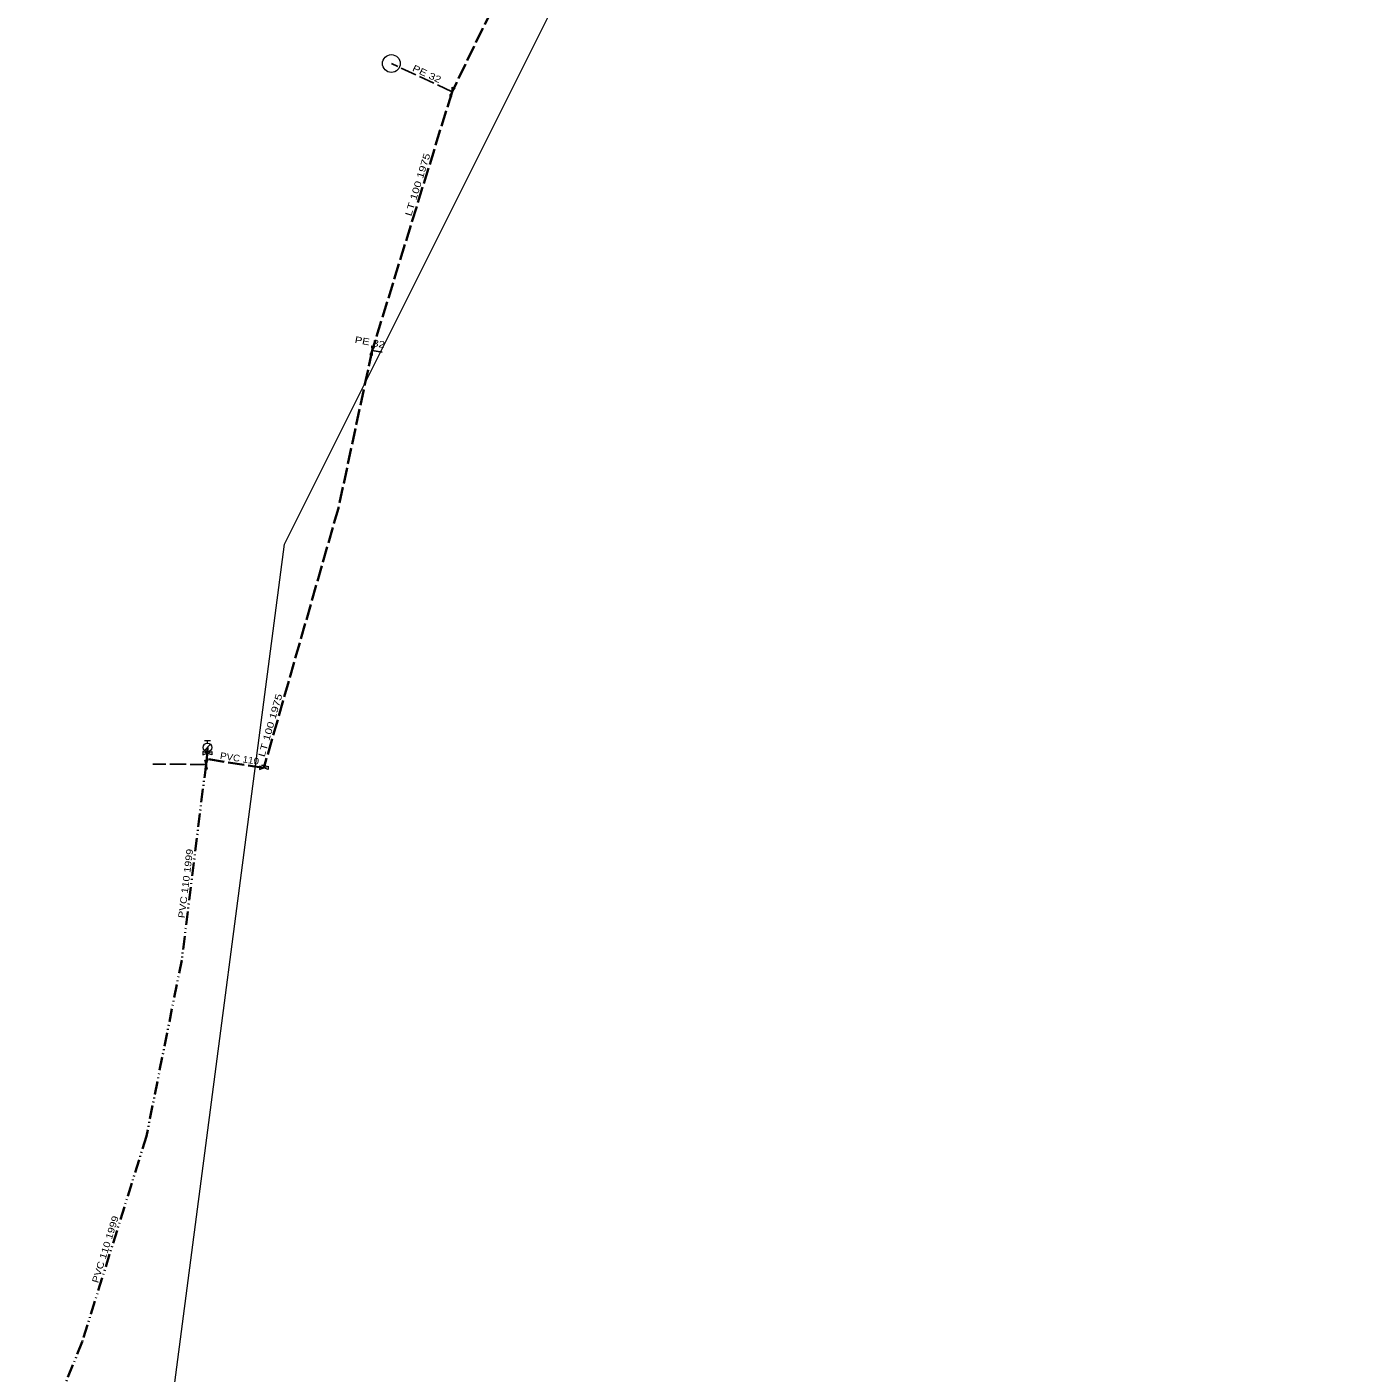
# Model space of a CAD drawing. Extents: x -582626 to -580899, y -1097611 to -1096610.
# Drawn here: x -581391.1 to -581240, y -1096912.4 to -1096761 of the extents above; entities that cross this region are included whole.
import ezdxf
from ezdxf.enums import TextEntityAlignment as Align

# ---------------------------------------------------------------- set-up
doc = ezdxf.new("R2010")
doc.units = 0
doc.header["$LTSCALE"] = 0.3
doc.linetypes.add('DASH_DOUBLE_DOT', pattern=[9.2, 5, -1.2, 0.3, -1.2, 0.3, -1.2])
doc.linetypes.add('LONG_DASHED', pattern=[7.5, 6, -1.5])
for name, color, linetype, lineweight in [('1', 7, 'Continuous', 13), ('10', 7, 'Continuous', 13), ('35', 7, 'LONG_DASHED', 35), ('36', 7, 'DASH_DOUBLE_DOT', 35), ('50', 7, 'LONG_DASHED', 25)]:
    doc.layers.add(name, color=color, linetype=linetype, lineweight=lineweight)
doc.layers.add('16', color=7, linetype='Continuous')
doc.layers.add('19', color=7, linetype='Continuous')

msp = doc.modelspace()

# ---------------------------------------------------------------- linework, layer by layer
at = {"layer": '1'}
msp.add_lwpolyline([(-582625.57, -1097394.66), (-582612.34, -1097467.421), (-582321.299, -1097262.369), (-581897.965, -1097202.837), (-581719.372, -1097182.994), (-581593.695, -1097110.233), (-581382.028, -1096971.327), (-581362.184, -1096819.192), (-581322.497, -1096739.817), (-581210.049, -1096733.202), (-581097.601, -1096686.9), (-580905.778, -1096719.973), (-580899.163, -1096627.369), (-581084.372, -1096614.14), (-581216.663, -1096680.285), (-581368.799, -1096686.9), (-581434.945, -1096812.577), (-581468.018, -1096971.327), (-581659.84, -1097004.4), (-581831.82, -1097110.233), (-582314.684, -1097169.765), (-582519.736, -1097295.442), (-582625.57, -1097394.66)], close=True, dxfattribs=at)
at = {"layer": '10'}
for p, q in [((-581371.181, -1096842.425), (-581370.474, -1096841.718)), ((-581371.177, -1096841.271), (-581370.477, -1096841.271)), ((-581370.827, -1096841.571), (-581370.827, -1096841.271)), ((-581370.85, -1096842.479), (-581371.1, -1096842.479)), ((-581364.487, -1096844.119), (-581364.737, -1096844.119))]:
    msp.add_line(p, q, dxfattribs=at)
for points in [[(-581343.31, -1096768.311), (-581343.291, -1096767.789), (-581343.007, -1096767.886), (-581343.31, -1096768.311), (-581343.613, -1096768.736), (-581343.329, -1096768.833)], [(-581352.301, -1096797.408), (-581352.334, -1096796.887), (-581352.042, -1096796.955), (-581352.301, -1096797.408), (-581352.56, -1096797.861), (-581352.268, -1096797.929)], [(-581370.994, -1096843.984), (-581371.144, -1096843.484), (-581370.844, -1096843.484), (-581370.994, -1096843.984), (-581371.144, -1096844.484), (-581370.844, -1096844.484)]]:
    msp.add_lwpolyline(points, close=True, dxfattribs=at)
for points in [[(-581370.85, -1096842.729), (-581370.35, -1096842.542), (-581370.35, -1096842.916), (-581370.85, -1096842.729), (-581371.35, -1096842.542), (-581371.35, -1096842.916), (-581370.85, -1096842.729), (-581370.85, -1096842.479), (-581370.6, -1096842.479)], [(-581364.487, -1096844.369), (-581363.987, -1096844.182), (-581363.987, -1096844.556), (-581364.487, -1096844.369), (-581364.987, -1096844.182), (-581364.987, -1096844.556), (-581364.487, -1096844.369), (-581364.487, -1096844.119), (-581364.237, -1096844.119)]]:
    msp.add_lwpolyline(points, dxfattribs=at)
for centre, radius in [((-581350.145, -1096765.14), 1), ((-581370.8268, -1096842.0707), 0.5)]:
    msp.add_circle(centre, radius, dxfattribs=at)
at = {"layer": '35'}
msp.add_line((-581364.487, -1096844.369), (-581370.918, -1096843.373), dxfattribs=at)
for points in [[(-581321.931, -1096700.577), (-581316.045, -1096715.422), (-581314.027, -1096722.581), (-581310.681, -1096727.605), (-581321.786, -1096737.077), (-581325.934, -1096741.538), (-581329.57, -1096745.504), (-581333.191, -1096749.465), (-581337.882, -1096757.099), (-581343.31, -1096768.311)], [(-581343.31, -1096768.311), (-581352.301, -1096797.408), (-581356.11, -1096815.163), (-581364.487, -1096844.369)], [(-581370.827, -1096842.071), (-581370.85, -1096842.729), (-581370.918, -1096843.373), (-581370.994, -1096843.984)]]:
    msp.add_lwpolyline(points, dxfattribs=at)
at = {"layer": '36'}
msp.add_lwpolyline([(-581370.994, -1096843.984), (-581373.727, -1096866.006), (-581377.691, -1096885.792), (-581384.916, -1096908.945), (-581388.633, -1096918.118)], dxfattribs=at)
at = {"layer": '50'}
for p, q in [((-581343.31, -1096768.311), (-581350.145, -1096765.14)), ((-581352.301, -1096797.408), (-581351.162, -1096797.613)), ((-581370.994, -1096843.984), (-581376.98, -1096843.946))]:
    msp.add_line(p, q, dxfattribs=at)

# ---------------------------------------------------------------- texts
at = {"layer": '16'}
for s, rotation, width, p in [('LT 100 1975', 72.829, 1.3, (-581346.8323, -1096778.8647)), ('LT 100 1975', 73.996, 1.3, (-581363.4018, -1096839.6794)), ('PVC 110', 351.196, 1.1, (-581367.2809, -1096843.6825)), ('PVC 110 1999', 82.926, 1.2, (-581372.9137, -1096857.4227)), ('PVC 110 1999', 72.669, 1.2, (-581381.962, -1096898.6382))]:
    msp.add_text(s, height=0.75, rotation=rotation, dxfattribs=dict(at, width=width)).set_placement(p, align=Align.CENTER)
at = {"layer": '19', "width": 1.25}
for rotation, p in [(335.112, (-581346.3118, -1096766.643)), (349.797, (-581352.6274, -1096796.8509))]:
    msp.add_text('PE 32', height=0.75, rotation=rotation, dxfattribs=at).set_placement(p, align=Align.CENTER)

doc.saveas('drawing.dxf')
